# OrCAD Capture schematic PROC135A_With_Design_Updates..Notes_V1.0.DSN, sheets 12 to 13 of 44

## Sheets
12 12. SOC POWER SUPPLY PMIC: size C; title: SOC POWER SUPPLY PMIC
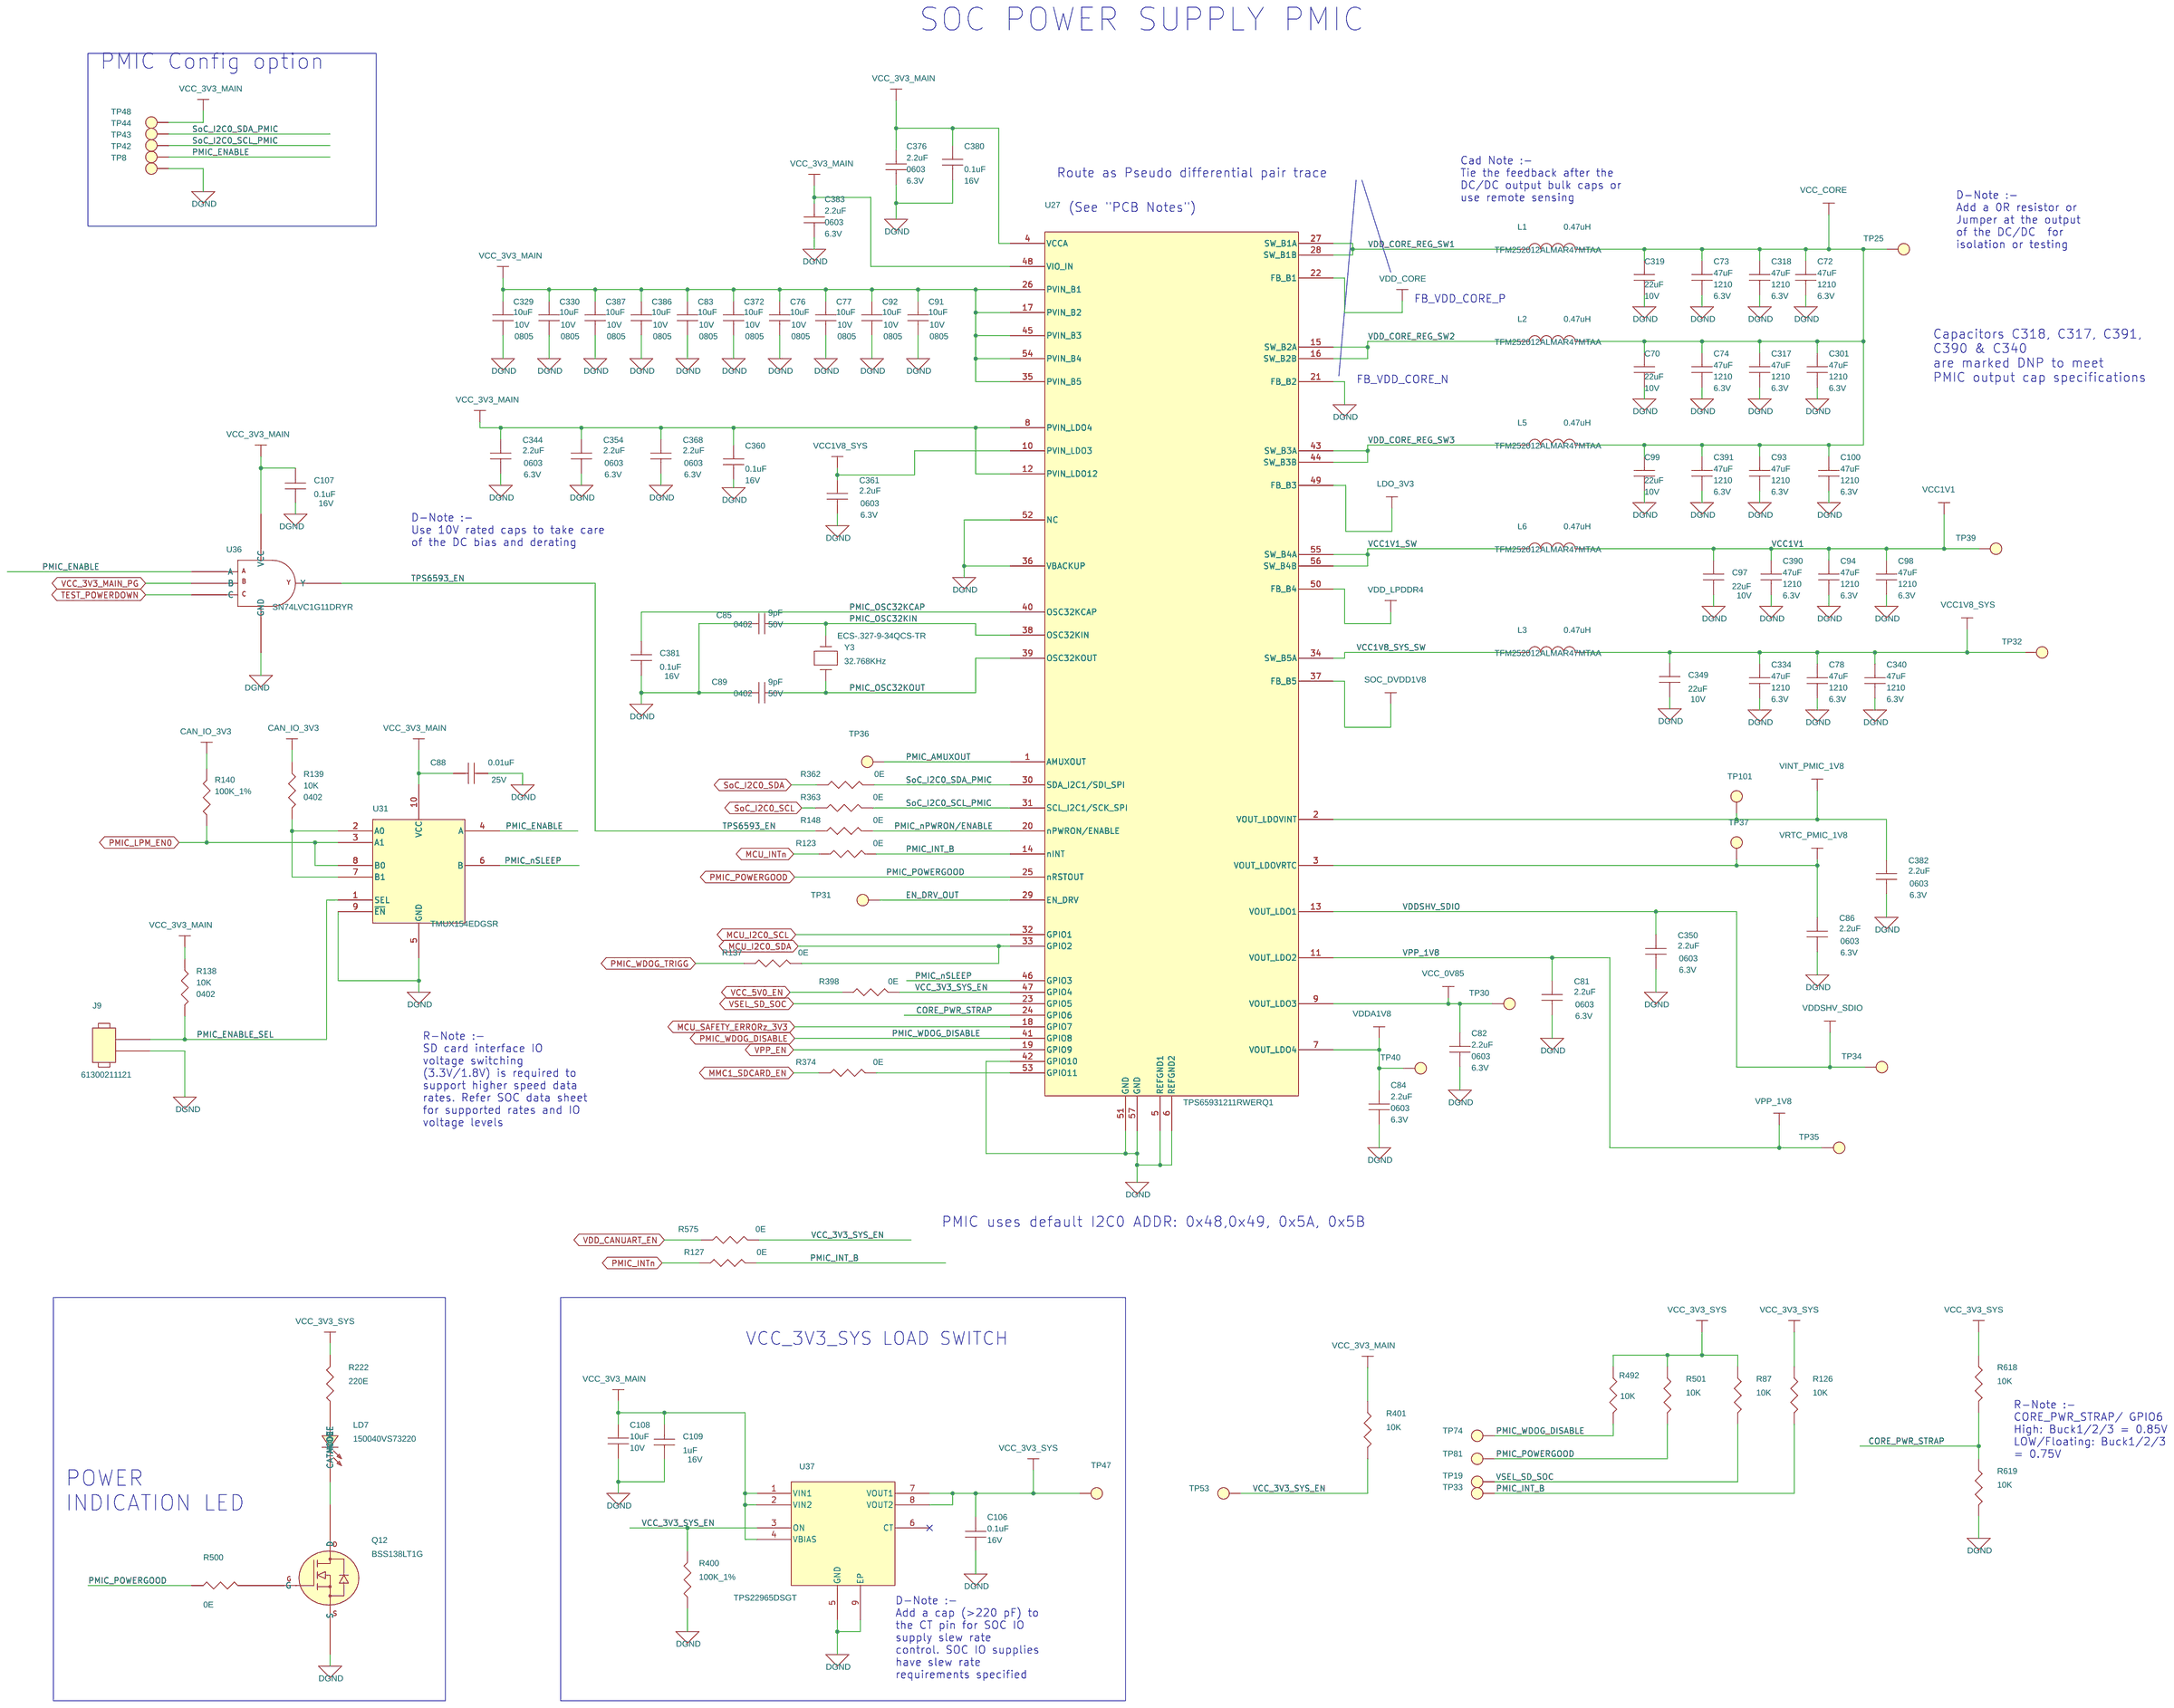
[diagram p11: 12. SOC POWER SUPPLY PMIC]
13 13. CURRENT MONITORING DEVICES: size C; title: CURRENT MONITORING DEVICES
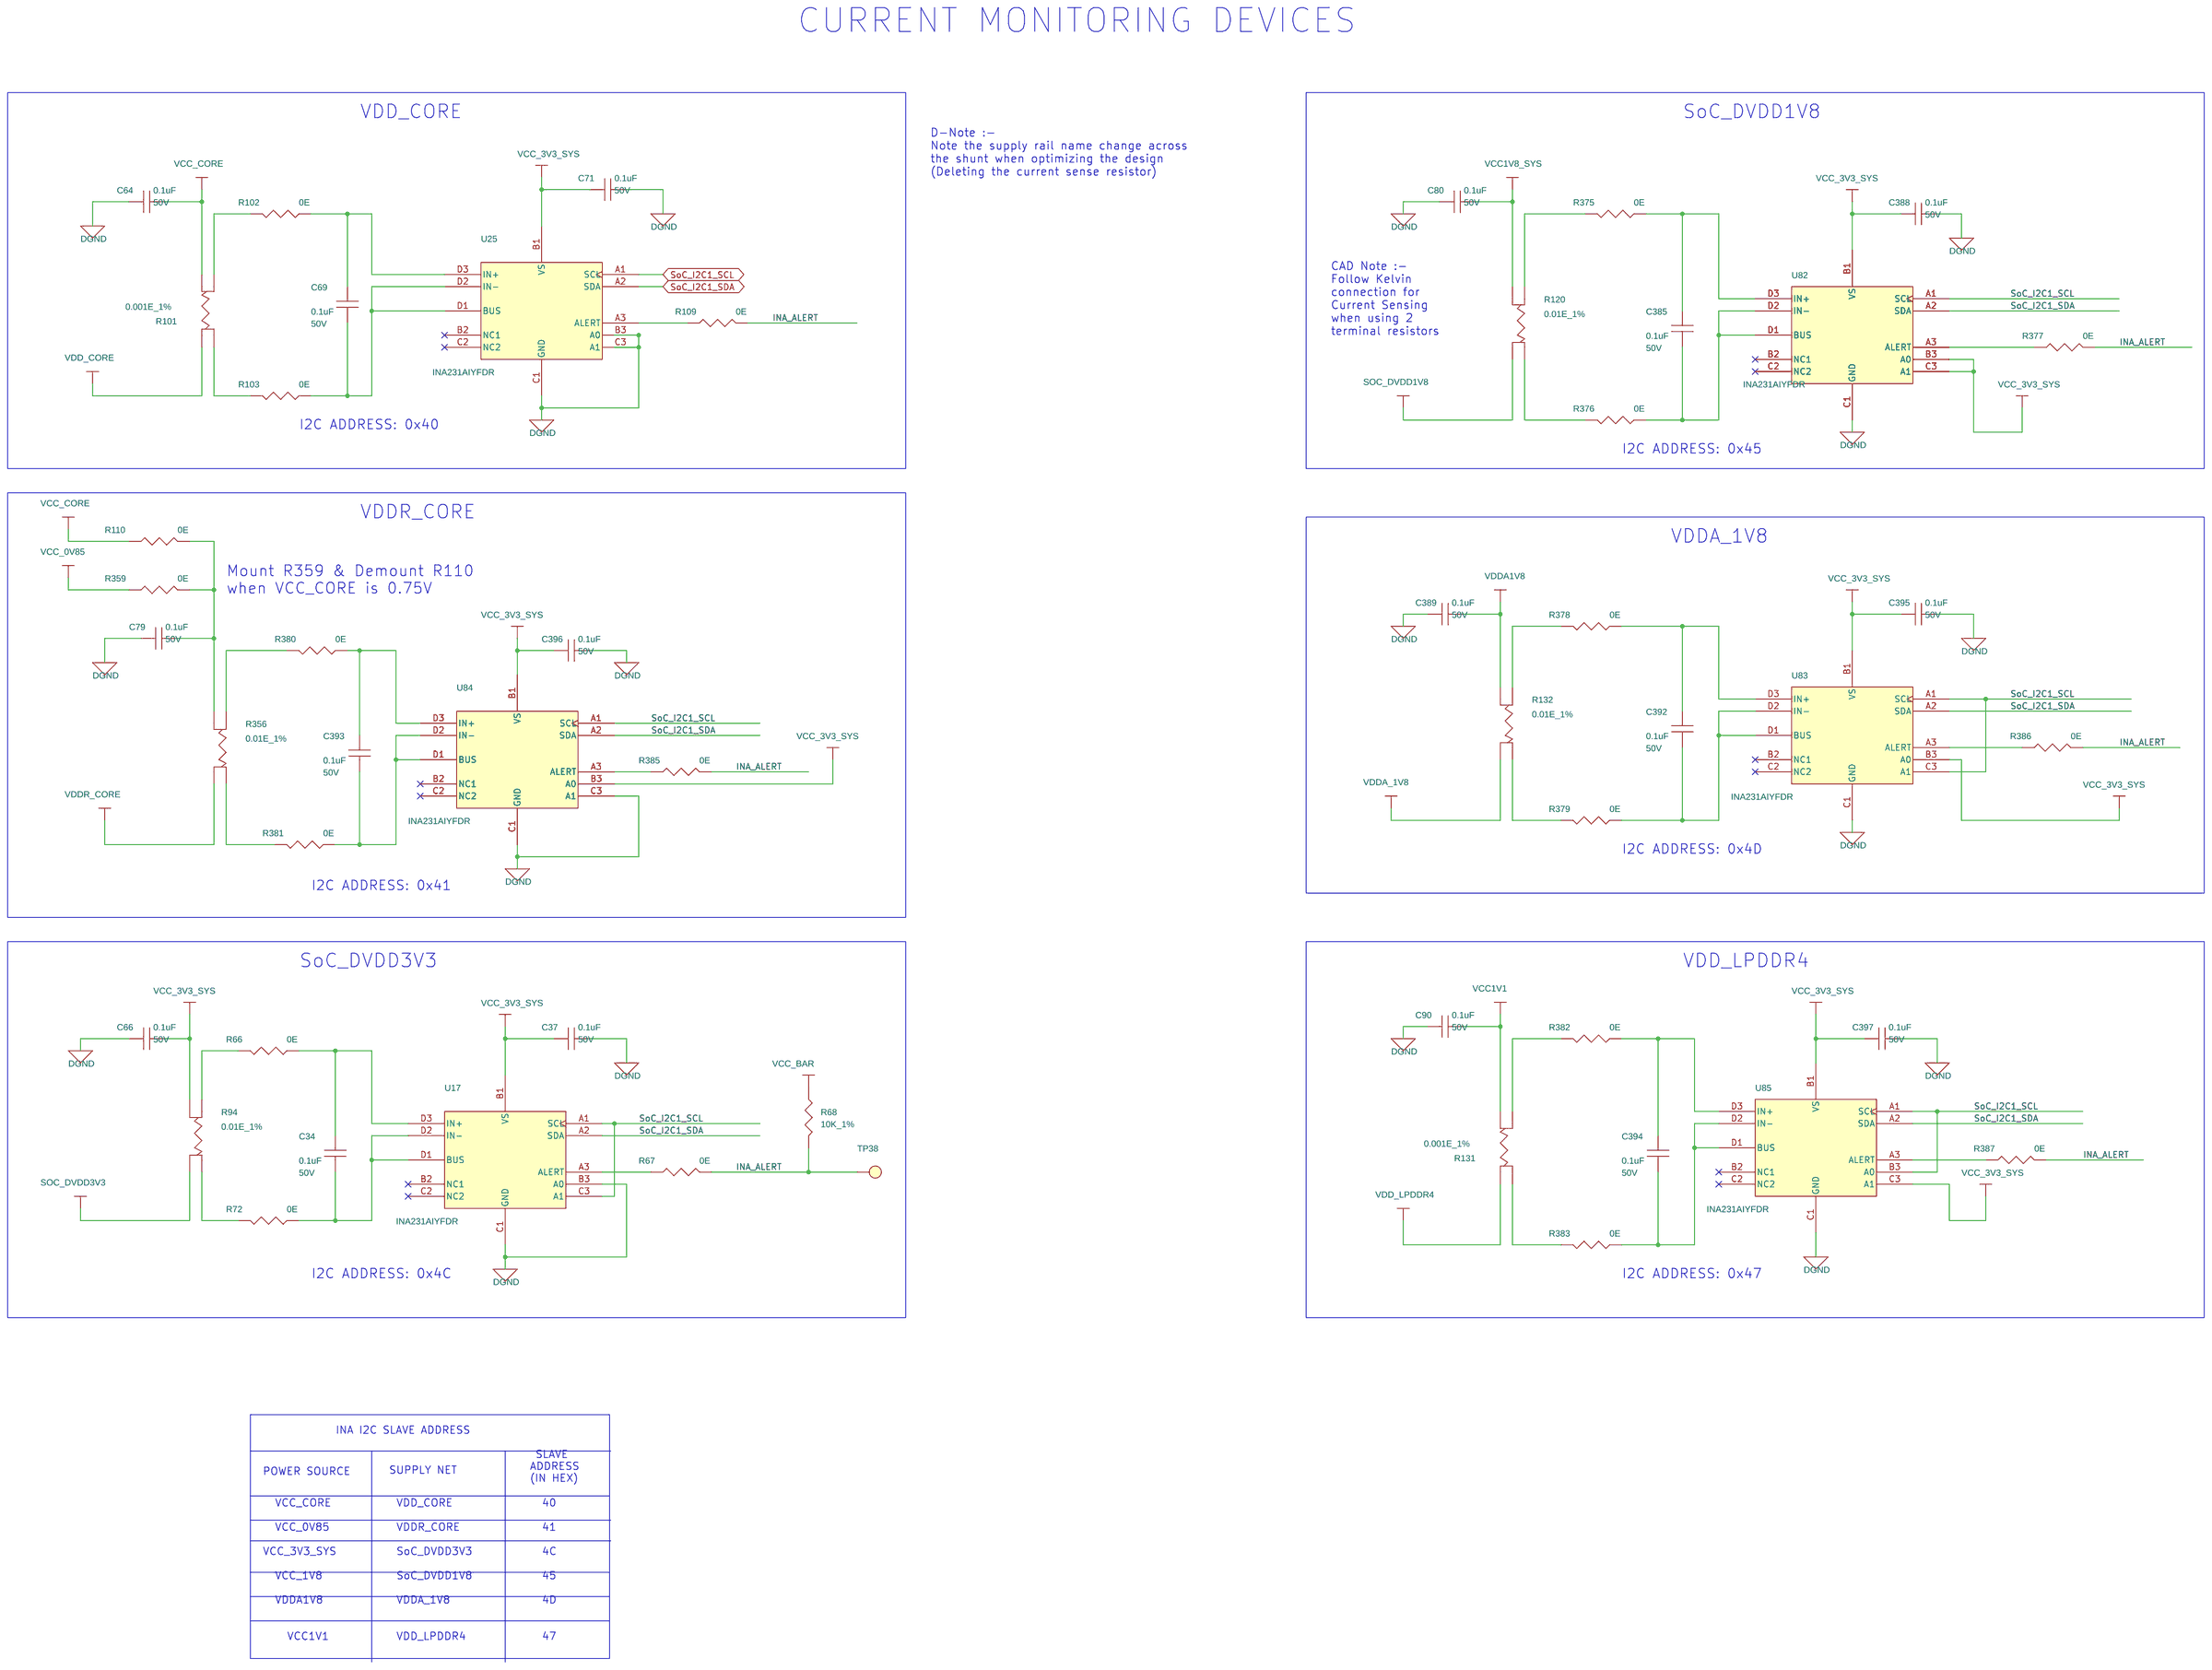
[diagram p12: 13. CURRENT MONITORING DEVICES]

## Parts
sheet 12. SOC POWER SUPPLY PMIC
C70  22uF  [CAP0603_1]
C72  47uF  [CAP1210_2-75]
C73  47uF  [CAP1210_2-75]
C74  47uF  [CAP1210_2-75]
C76  10uF  [CAP0805_1-5]
C77  10uF  [CAP0805_1-5]
C78  47uF  [CAP1210_2-75]
C81  2.2uF  [CAP0603_1]
C82  2.2uF  [CAP0603_1]
C83  10uF  [CAP0805_1-5]
C84  2.2uF  [CAP0603_1]
C85  9pF  [CAP0402_0-75]
C86  2.2uF  [CAP0603_1]
C88  0.01uF  [CAP0201_0-5]
C89  9pF  [CAP0402_0-75]
C91  10uF  [CAP0805_1-5]
C92  10uF  [CAP0805_1-5]
C93  47uF  [CAP1210_2-75]
C94  47uF  [CAP1210_2-75]
C97  22uF  [CAP0603_1]
C98  47uF  [CAP1210_2-75]
C99  22uF  [CAP0603_1]
C100  47uF  [CAP1210_2-75]
C106  0.1uF  [CAP0201_0-5]
C107  0.1uF  [CAP0201_0-5]
C108  10uF  [CAP0402_0-75]
C109  1uF  [CAP0201_0-5]
C301  47uF  [CAP1210_2-75]
C317  47uF  [CAP1210_2-75]
C318  47uF  [CAP1210_2-75]
C319  22uF  [CAP0603_1]
C329  10uF  [CAP0805_1-5]
C330  10uF  [CAP0805_1-5]
C334  47uF  [CAP1210_2-75]
C340  47uF  [CAP1210_2-75]
C344  2.2uF  [CAP0603_1]
C349  22uF  [CAP0603_1]
C350  2.2uF  [CAP0603_1]
C354  2.2uF  [CAP0603_1]
C360  0.1uF  [CAP0201_0-5]
C361  2.2uF  [CAP0603_1]
C368  2.2uF  [CAP0603_1]
C372  10uF  [CAP0805_1-5]
C376  2.2uF  [CAP0603_1]
C380  0.1uF  [CAP0201_0-5]
C381  0.1uF  [CAP0201_0-5]
C382  2.2uF  [CAP0603_1]
C383  2.2uF  [CAP0603_1]
C386  10uF  [CAP0805_1-5]
C387  10uF  [CAP0805_1-5]
C390  47uF  [CAP1210_2-75]
C391  47uF  [CAP1210_2-75]
J9  HDR_1X2  [HDR_1X2_61300211121_S_T_8-6]
L1  0.47uH  [IND1008_1-2]
L2  0.47uH  [IND1008_1-2]
L3  0.47uH  [IND1008_1-2]
L5  0.47uH  [IND1008_1-2]
L6  0.47uH  [IND1008_1-2]
LD7  150040VS73220  [LED_150040GS73220_40X20_SMD_0-4]
Q12  BSS138LT1G  [SOT23-123_1-2]
R87  10K  [RES0201_0-5]
R123  0E  [RES0201_0-5]
R126  10K  [RES0201_0-5]
R127  0E  [RES0201_0-5]
R137  0E  [RES0201_0-5]
R138  10K  [RES0402_0-5]
R139  10K  [RES0402_0-5]
R140  100K_1%  [RES0402_0-5]
R148  0E  [RES0201_0-5]
R222  220E  [RES0402_0-5]
R362  0E  [RES0201_0-5]
R363  0E  [RES0201_0-5]
R374  0E  [RES0201_0-5]
R398  0E  [RES0201_0-5]
R400  100K_1%  [RES0402_0-5]
R401  10K  [RES0201_0-5]
R492  10K  [RES0201_0-5]
R500  0E  [RES0201_0-5]
R501  10K  [RES0201_0-5]
R575  0E  [RES0201_0-5]
R618  10K  [RES0201_0-5]
R619  10K  [RES0201_0-5]
TP8  TP40_SMD  [TP40_SMD]
TP19  TP20_SMD  [TP20_SMD]
TP25  TP20_SMD  [TP20_SMD]
TP30  TP20_SMD  [TP20_SMD]
TP31  TP30_SMD  [TP30_SMD]
TP32  TP20_SMD  [TP20_SMD]
TP33  TP20_SMD  [TP20_SMD]
TP34  TP20_SMD  [TP20_SMD]
TP35  TP20_SMD  [TP20_SMD]
TP36  TP20_SMD  [TP20_SMD]
TP37  TP20_SMD  [TP20_SMD]
TP39  TP20_SMD  [TP20_SMD]
TP40  TP20_SMD  [TP20_SMD]
TP42  TP40_SMD  [TP40_SMD]
TP43  TP40_SMD  [TP40_SMD]
TP44  TP40_SMD  [TP40_SMD]
TP47  TP20_SMD  [TP20_SMD]
TP48  TP40_SMD  [TP40_SMD]
TP53  TP20_SMD  [TP20_SMD]
TP74  TP30_SMD  [TP30_SMD]
TP81  TP20_SMD  [TP20_SMD]
TP101  TP20_SMD  [TP20_SMD]
U27  TPS65931211RWERQ1  [VQFN56_19-68_320X320_0-9_EP6]
U31  TMUX154EDGSR  [MSOP10_19-68_120X120_1-1]
U36  SN74LVC1G11DRYR  [SON6_SN74LVC2G17_40X60_0-6]
U37  TPS22965DSGT  [WSON8_19-68_80X80_0-8]
Y3  32.768KHz  [XTAL_ECS-32_130X60_SMD_0-9]
sheet 13. CURRENT MONITORING DEVICES
C34  0.1uF  [CAP0402_0-75]
C37  0.1uF  [CAP0402_0-75]
C64  0.1uF  [CAP0402_0-75]
C66  0.1uF  [CAP0402_0-75]
C69  0.1uF  [CAP0402_0-75]
C71  0.1uF  [CAP0402_0-75]
C79  0.1uF  [CAP0402_0-75]
C80  0.1uF  [CAP0402_0-75]
C90  0.1uF  [CAP0402_0-75]
C385  0.1uF  [CAP0402_0-75]
C388  0.1uF  [CAP0402_0-75]
C389  0.1uF  [CAP0402_0-75]
C392  0.1uF  [CAP0402_0-75]
C393  0.1uF  [CAP0402_0-75]
C394  0.1uF  [CAP0402_0-75]
C395  0.1uF  [CAP0402_0-75]
C396  0.1uF  [CAP0402_0-75]
C397  0.1uF  [CAP0402_0-75]
R66  0E  [RES0402_0-5]
R67  0E  [RES0201_0-5]
R68  10K_1%  [RES0201_0-5]
R72  0E  [RES0402_0-5]
R94  0.01E_1%  [RES_KRL3216T4_1206-4_0-7]
R101  0.001E_1%  [RES_CST0612_0612-4_0-9]
R102  0E  [RES0402_0-5]
R103  0E  [RES0402_0-5]
R109  0E  [RES0201_0-5]
R110  0E  [RES0603_0-75]
R120  0.01E_1%  [RES_KRL3216T4_1206-4_0-7]
R131  0.001E_1%  [RES_CST0612_0612-4_0-9]
R132  0.01E_1%  [RES_KRL3216T4_1206-4_0-7]
R356  0.01E_1%  [RES_KRL3216T4_1206-4_0-7]
R359  0E  [RES0603_0-75]
R375  0E  [RES0402_0-5]
R376  0E  [RES0402_0-5]
R377  0E  [RES0201_0-5]
R378  0E  [RES0402_0-5]
R379  0E  [RES0402_0-5]
R380  0E  [RES0402_0-5]
R381  0E  [RES0402_0-5]
R382  0E  [RES0402_0-5]
R383  0E  [RES0402_0-5]
R385  0E  [RES0201_0-5]
R386  0E  [RES0201_0-5]
R387  0E  [RES0201_0-5]
TP38  TP20_SMD  [TP20_SMD]
U17  INA231AIYFDR  [DSBGA12_15-74_60X70_0-4]
U25  INA231AIYFDR  [DSBGA12_15-74_60X70_0-4]
U82  INA231AIYFDR  [DSBGA12_15-74_60X70_0-4]
U83  INA231AIYFDR  [DSBGA12_15-74_60X70_0-4]
U84  INA231AIYFDR  [DSBGA12_15-74_60X70_0-4]
U85  INA231AIYFDR  [DSBGA12_15-74_60X70_0-4]

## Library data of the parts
C70 C97 C99 C319 C349 = CAP: CAP CERAMIC 22uF 10V 20% X5R 0603; Chkd/date: MANIRAJA/230118; Crtd /date: MANIRAJA/230118; Custom_Duty: 15%; Customs_HS_Code: 85322990; Distributor_name: DIGIKEY; Distributor_part_number: 490-10476-1-ND; Footprint Path: Y:\MIS_DATABASE\Library\ALTIUM_TOOL\PCB_FOOTPRINTS\Altium_Footprint_Lib.PcbLib; Height: 1.00MM; Library Path: Y:\MIS_DATABASE\Library\ALTIUM_TOOL\SCHEMATICS_PARTS\MS_DISCRETE_Library.schlib; Manufacturer: MURATA; Mfr_name: MURATA; Mfr_part_number: GRM188R61A226ME15D; Mistral Part No: 120014100009-R; Package: 0603; Part_type: CAPACITORS\CERAMIC; Project: TI_MAXIE_CPB; RoHS: RoHS; Temperature: -55°C+85°C; Tolerance: 20%; Voltage: 10V; Wattage: NA; Weight: 6.3mg; Datasheet: Y:\MIS_DATABASE\DATASHEETS\CAPACITORS\GRM188R61A226ME15.PDF
C72-C74 C78 C93 C94 C98 C100 C301 C317 C318 C334 C340 C390 C391 = CAP: CAP CERAMIC 47uF 6.3V 10% X7R AUTO 1210; Automotive Alternate_mfr_name: TDK; Automotive Alternate_mfr_part_number: CGA6P1X7S1A476M; Chkd/date: MANIRAJA/280918; Crtd /date: ALVY/280918; Custom_Duty: 15%; Customs_HS_Code: 85322990; Direct Alternate_mfr_name: TDK; Direct Alternate_mfr_part_number: CGA6P1X7S1A476M; Distributor_name: DIGIKEY; Distributor_part_number: 490-4844-1-ND; Footprint Path: Y:\MIS_DATABASE\Library\ALTIUM_TOOL\PCB_FOOTPRINTS\Altium_Footprint_Lib.PcbLib; Height: 2.70MM; Library Path: Y:\MIS_DATABASE\Library\ALTIUM_TOOL\SCHEMATICS_PARTS\MS_DISCRETE_Library.schlib; Mfr_name: MURATA; Mfr_part_number: GCM32ER70J476KE19L; Mistral Part No: 120018090056-R; Package: 1210; Part_type: CAPACITORS\CERAMIC; Project: TI_J7_SVB-DUT; RoHS: RoHS; Temperature: -55°C+125°C; Tolerance: 10%; Voltage: 6.3V; Wattage: NA; Weight: 110mg; Datasheet: Y:\MIS_DATABASE\DATASHEETS\CAPACITORS\MURATA-GCM-SER.PDF
C76 C77 C83 C91 C92 C329 C330 C372 C386 C387 = CAP: CAP CERAMIC 10uF 10V 10% X7R AUTO 0805; Automotive Alternate_mfr_name: MURATA; Automotive Alternate_mfr_part_number: GCM21BR71A106KE22L; Chkd/date: MANIRAJA/080419; Crtd /date: ALVY/050419; Custom_Duty: 15%; Customs_HS_Code: 85322990; Direct Alternate_mfr_name: SAMSUNG; Direct Alternate_mfr_part_number: CL21B106KPQNNNE; Distributor_name: DIGIKEY; Distributor_part_number: 490-14531-1-ND; Footprint Path: Y:\MIS_DATABASE\Library\ALTIUM_TOOL\PCB_FOOTPRINTS\Altium_Footprint_Lib.PcbLib; Height: 1.40MM; Library Path: Y:\MIS_DATABASE\Library\ALTIUM_TOOL\SCHEMATICS_PARTS\MS_DISCRETE_Library.schlib; Mfr_name: MURATA; Mfr_part_number: GCM21BR71A106KE22K; Mistral Part No: 120019040010-R; Package: 0805; Part_type: CAPACITORS\CERAMIC; Project: J7ES_SOM_DUAL-LEO_PMIC; RoHS: RoHS; Temperature: -55°C+125°C; Tolerance: 10%; Voltage: 10V; Wattage: NA; Weight: 9.5mg; Datasheet: Y:\MIS_DATABASE\DATASHEETS\CAPACITORS\GCM21BR71A106KE22.PDF
C81 C82 C84 C86 C344 C350 C354 C361 C368 C376 C382 C383 = CAP: CAP CERAMIC 2.2uF 6.3V 10% X7R AUTO 0603; Automotive Alternate_mfr_name: TDK; Automotive Alternate_mfr_part_number: CGA3E1X7R0J225K080AC; Chkd/date: MANIRAJA/050419; Crtd /date: ALVY/050419; Custom_Duty: 15%; Customs_HS_Code: 85322990; Direct Alternate_mfr_name: TDK; Direct Alternate_mfr_part_number: CGA3E1X7R0J225K080AC; Distributor_name: DIGIKEY; Distributor_part_number: 490-5316-1-ND; Footprint Path: Y:\MIS_DATABASE\Library\ALTIUM_TOOL\PCB_FOOTPRINTS\Altium_Footprint_Lib.PcbLib; Height: 0.90MM; Library Path: Y:\MIS_DATABASE\Library\ALTIUM_TOOL\SCHEMATICS_PARTS\MS_DISCRETE_Library.schlib; Mfr_name: MURATA; Mfr_part_number: GCM188R70J225KE22D; Mistral Part No: 120019040009-R; Package: 0603; Part_type: CAPACITORS\CERAMIC; Project: J7ES_SOM_DUAL-LEO_PMIC; RoHS: RoHS; Temperature: -55°C+125°C; Tolerance: 10%; Voltage: 6.3V; Wattage: NA; Weight: 6.3mg; Datasheet: Y:\MIS_DATABASE\DATASHEETS\CAPACITORS\GCM188R70J225KE22.PDF
C85 C89 = CAP: CAP CERAMIC 9pF 50V 0.5pF C0G(NP0) AUTO 0402; Automotive Alternate_mfr_name: TDK; Automotive Alternate_mfr_part_number: CGA2B2C0G1H090D050BA; Chkd/date: MANIRAJA/290121; Crtd /date: ALVY/270121; Custom_Duty: 15%; Customs_HS_Code: 85322990; Direct Alternate_mfr_name: TDK; Direct Alternate_mfr_part_number: CGA2B2C0G1H090D050BA; Distributor_name: DIGIKEY; Distributor_part_number: GCM1555C1H9R0DA16D-ND; Footprint Path: Y:\MIS_DATABASE\Library\ALTIUM_TOOL\PCB_FOOTPRINTS\Altium_Footprint_Lib.PcbLib; Height: 0.55MM; Library Path: Y:\MIS_DATABASE\Library\ALTIUM_TOOL\SCHEMATICS_PARTS\MS_DISCRETE_Library.schlib; Mfr_name: MURATA; Mfr_part_number: GCM1555C1H9R0DA16D; Mistral Part No: 120021010034-R; Package: 0402; Part_type: CAPACITORS\CERAMIC; Project: TI_DRA829 SK EVM BRD; RoHS: RoHS; Temperature: -55°C+125°C; Tolerance: 0.5pF%; Voltage: 50V; Wattage: NA; Weight: 1.6mg; Datasheet: Y:\MIS_DATABASE\DATASHEETS\CAPACITORS\MURATA-GCM-SER.PDF
C88 = CAP: CAP CERAMIC 0.01uF 25V 10% X5R 0201; Chkd/date: MANIRAJA/230118; Crtd /date: MANIRAJA/230118; Custom_Duty: 15%; Customs_HS_Code: 85322990; Distributor_name: DIGIKEY; Distributor_part_number: GRM033R61E103KA12J-ND; Footprint Path: Y:\MIS_DATABASE\Library\ALTIUM_TOOL\PCB_FOOTPRINTS\Altium_Footprint_Lib.PcbLib; Height: 0.33MM; Library Path: Y:\MIS_DATABASE\Library\ALTIUM_TOOL\SCHEMATICS_PARTS\MS_DISCRETE_Library.schlib; Mfr_name: MURATA; Mfr_part_number: GRM033R61E103KA12J; Mistral Part No: 120018010007-R; Package: 0201; Part_type: CAPACITORS\CERAMIC; Project: TI_MAXIE_CPB; RoHS: RoHS; Temperature: -55°C+85°C; Tolerance: 10%; Voltage: 25V; Wattage: NA; Weight: 0.33mg; Datasheet: Y:\MIS_DATABASE\DATASHEETS\CAPACITORS\GRM033R61E103KA12.PDF
C106 C107 = CAP: CAP CERAMIC 0.1uF 16V 10% X5R 0201; Alt_Mfr_name: YAGEO AMERICA; Alt_Mfr_part_number: CC0402KRX5R8BB104; Chkd/date: MANIRAJA/230118; Crtd /date: MANIRAJA/230118; Custom_Duty: 15%; Customs_HS_Code: 85322990; Distributor_name: DIGIKEY; Distributor_part_number: 490-14305-1-ND; Footprint Path: Y:\MIS_DATABASE\Library\ALTIUM_TOOL\PCB_FOOTPRINTS\Altium_Footprint_Lib.PcbLib; Height: 0.33MM; Library Path: Y:\MIS_DATABASE\Library\ALTIUM_TOOL\SCHEMATICS_PARTS\MS_DISCRETE_Library.schlib; Mfr_name: MURATA; Mfr_part_number: GRM033R61C104KE14D; Mistral Part No: 120009030072-R; Package: 0201; Part_type: CAPACITORS\CERAMIC; Project: TI_MAXIE_CPB; RoHS: RoHS; Temperature: -55°C+85°C; Tolerance: 10%; Voltage: 16V; Wattage: NA; Weight: 0.33mg; Datasheet: Y:\MIS_DATABASE\DATASHEETS\CAPACITORS\GRM033R61C104KE14.PDF
C108 = CAP: CAP CERAMIC 10uF 10V 20% X5R 0402; Chkd/date: MANIRAJA/300520; Crtd /date: ALVY/260520; Custom_Duty: 15%; Customs_HS_Code: 85322990; Distributor_name: DIGIKEY; Distributor_part_number: 490-GRM155R61A106ME11DTR-ND; Footprint Path: Y:\MIS_DATABASE\Library\ALTIUM_TOOL\PCB_FOOTPRINTS\Altium_Footprint_Lib.PcbLib; Height: 0.55MM; Library Path: Y:\MIS_DATABASE\Library\ALTIUM_TOOL\SCHEMATICS_PARTS\MS_DISCRETE_Library.schlib; Mfr_name: MURATA; Mfr_part_number: GRM155R61A106ME11D; Mistral Part No: 120013110019-R; Package: 0402; Part_type: CAPACITORS\CERAMIC; Project: QCS610_NANOSOM; RoHS: RoHS; Temperature: -55°C+85°C; Tolerance: 20%; Voltage: 10V; Wattage: NA; Weight: 3.1mg; Datasheet: Y:\MIS_DATABASE\DATASHEETS\CAPACITORS\MURATA-GXX-SER_NOV17.PDF
C109 = CAP: CAP CERAMIC 1uF 16V 20% X5R 0201; Chkd/date: MANIRAJA/300520; Crtd /date: ALVY/260520; Custom_Duty: 15%; Customs_HS_Code: 85322990; Distributor_name: DIGIKEY; Distributor_part_number: 490-18654-1-ND; Footprint Path: Y:\MIS_DATABASE\Library\ALTIUM_TOOL\PCB_FOOTPRINTS\Altium_Footprint_Lib.PcbLib; Height: 0.39MM; Library Path: Y:\MIS_DATABASE\Library\ALTIUM_TOOL\SCHEMATICS_PARTS\MS_DISCRETE_Library.schlib; Mfr_name: MURATA; Mfr_part_number: GRM033R61C105ME15D; Mistral Part No: 120018090038-R; Package: 0201; Part_type: CAPACITORS\CERAMIC; Project: QCS610_NANOSOM; RoHS: RoHS; Temperature: -55°C+85°C; Tolerance: 20%; Voltage: 16V; Wattage: NA; Weight: 0.33mg; Datasheet: Y:\MIS_DATABASE\DATASHEETS\CAPACITORS\GRM033R61C105ME15.PDF
C360 C380 C381 = CAP: CAP CERAMIC 0.1uF 16V 10% X7S AUTO 0201; Chkd/date: MANIRAJA/110321; Crtd /date: ALVY/110321; Custom_Duty: 15%; Customs_HS_Code: 85322990; Distributor_name: DIGIKEY; Distributor_part_number: 490-GRT033C71C104KE01DTR-ND; Height: 0.33MM; Mfr_name: MURATA; Mfr_part_number: GRT033C71C104KE01D; Mistral Part No: 120021030007-R; Package: 0201; Part_type: CAPACITORS\CERAMIC; Project: J7ES_SK_BRD; RoHS: RoHS; Temperature: -55°C+125°C; Tolerance: 10%; Voltage: 16V; Wattage: NA; Weight: 330mg; Datasheet: Y:\MIS_DATABASE\DATASHEETS\CAPACITORS\GRT033C71C104KE01.PDF
J9 = HEADER_2X1: CON HDR 1X2 2.54MM PITCH ST TH; Chkd/date: MANIRAJA/031018; Crtd /date: ALVY/031018; Custom_Duty: 24%; Customs_HS_Code: 85369090; Distributor_name: DIGIKEY; Distributor_part_number: 732-5315-ND; Footprint Path: Y:\MIS_DATABASE\Library\ALTIUM_TOOL\PCB_FOOTPRINTS\Altium_Footprint_Lib.PcbLib; Height: 8.54MM; Library Path: Y:\MIS_DATABASE\Library\ALTIUM_TOOL\SCHEMATICS_PARTS\MS_CONNECTOR_Library.schlib; Mfr_name: WURTH ELECTRONICS; Mfr_part_number: 61300211121; Mistral Part No: 150018100003-R; Package: THRU-HOLE; Part_type: CONNECTOR\HEADERS; Project: ALPINE_EVM; RoHS: RoHS; Temperature: -40°C+105°C; Tolerance: NA; Voltage: NA; Wattage: NA; Weight: 120mg; Datasheet: Y:\MIS_DATABASE\DATASHEETS\CONNECTORS\6130XXX.PDF
L1-L3 L5 L6 = INDUCTOR: IND POWER 0.47uH 20% 4.9A 1008; Chkd/date: VASANTHA/010419; Crtd /date: ALVY/010419; Custom_Duty: 24%; Customs_HS_Code: 85437099; Distributor_name: DIGIKEY; Distributor_part_number: 445-181489-1-ND; Footprint Path: Y:\MIS_DATABASE\Library\ALTIUM_TOOL\PCB_FOOTPRINTS\Altium_Footprint_Lib.PcbLib; Height: 1.20MM; Library Path: Y:\MIS_DATABASE\Library\ALTIUM_TOOL\SCHEMATICS_PARTS\MS_DISCRETE_Library.schlib; Mfr_name: TDK CORPORATION; Mfr_part_number: TFM252012ALMAR47MTAA; Mistral Part No: 130019040001-R; Package: 1008; Project: J7ES_SOM_DUAL-LEO_PMIC; RoHS: RoHS; Temperature: -55°C+150°C; Tolerance: 20%; Voltage: NA; Wattage: NA; Weight: NA; Datasheet: Y:\MIS_DATABASE\DATASHEETS\DISCRETES\INDUCTORS\TFM252012ALMA-SER.PDF
LD7 = DIODE_LED: DIODE LED BRIGHT GREEN SMD; Chkd/date: MANIRAJA/261120; Crtd /date: ALVY/261120; Custom_Duty: 24%; Customs_HS_Code: 85439000; Distributor_name: DIGIKEY; Distributor_part_number: 732-13425-1-ND; Footprint Path: Y:\MIS_DATABASE\Library\ALTIUM_TOOL\PCB_FOOTPRINTS\Altium_Footprint_Lib.PcbLib; Height: 0.35MM; Library Path: Y:\MIS_DATABASE\Library\ALTIUM_TOOL\SCHEMATICS_PARTS\MS_OPTO_Library.schlib; Mfr_name: WURTH ELECTRONIK; Mistral Part No: 130020110071-R; Package: SMD; Part_type: OPTO\LED; Project: AM64X_SKEVM; RoHS: RoHS; Temperature: -40°C+85°C; Tolerance: NA; Voltage: NA; Wattage: NA; Weight: 29.3mg; Datasheet: Y:\MIS_DATABASE\DATASHEETS\DISCRETES\LEDS\150040VS73220.PDF
Q12 = MOSFET_BSS138W: IC MOSFET N-CHANNEL 50V 200mA SOT23-3; Chkd/date: MANIRAJA/250219; Crtd /date: JEBRAN/060416; Custom_Duty: 15%; Customs_HS_Code: 85423100; Distributor_name: DIGIKEY; Distributor_part_number: BSS138LT1GOSCT-ND; Footprint Path: Y:\MIS_DATABASE\Library\ALTIUM_TOOL\PCB_FOOTPRINTS\Altium_Footprint_Lib.PcbLib; Height: 1.11MM; Library Path: Y:\MIS_DATABASE\Library\ALTIUM_TOOL\SCHEMATICS_PARTS\MS_MOSFET_Library.schlib; Mfr_name: ON SEMICONDUCTOR; Mistral Part No: 142016040001-R; Package: SOT23-3; Part_type: ICS\POWER\MOSFET; Project: LRDE_ABCM; RoHS: RoHS; Temperature: -55°C+150°C; Tolerance: NA; Voltage: NA; Wattage: NA; Weight: 8mg; Datasheet: Y:\MIS_DATABASE\DATASHEETS\DISCRETES\TRANSISTORS_FETS\BSS138LT1G.PDF
R87 R126 R401 R492 R501 R618 R619 = RESISTOR: RES 10K 1/20W 5% 0201; Chkd/date: MANIRAJA/050517; Crtd /date: MANIRAJA/050517; Custom_Duty: 15%; Customs_HS_Code: 85332119; Distributor_name: DIGIKEY; Distributor_part_number: 311-10KNCT-ND; Footprint Path: Y:\MIS_DATABASE\Library\ALTIUM_TOOL\PCB_FOOTPRINTS\Altium_Footprint_Lib.PcbLib; Height: 0.26MM; Library Path: Y:\MIS_DATABASE\Library\ALTIUM_TOOL\SCHEMATICS_PARTS\MS_DISCRETE_Library.schlib; Mfr_name: YAGEO AMERICA; Mfr_part_number: RC0201JR-0710KL; Mistral Part No: 110010070051-R; Package: 0201; Part_type: RESISTORS\FIXED; Project: GOLDEN-I LITE; RoHS: RoHS; Temperature: -55°C+125°C; Tolerance: 5%; Voltage: NA; Wattage: 1/20W; Weight: 0.17mg; Datasheet: Y:\MIS_DATABASE\DATASHEETS\RESISTORS\RCXXXXL-SER_MAR18.PDF
R67 R109 R123 R137 R374 R377 R385-R387 R398 R575 = RESISTOR: RES 0E 1/20W 5% 0201; Chkd/date: NAVEED/301214; Crtd /date: MUDDU/120710; Custom_Duty: 15%; Customs_HS_Code: 85332119; Distributor_name: DIGIKEY; Distributor_part_number: 311-0.0NCT-ND; Footprint Path: Y:\MIS_DATABASE\Library\ALTIUM_TOOL\PCB_FOOTPRINTS\Altium_Footprint_Lib.PcbLib; Height: 0.26MM; Library Path: Y:\MIS_DATABASE\Library\ALTIUM_TOOL\SCHEMATICS_PARTS\MS_DISCRETE_Library.schlib; Mfr_name: YAGEO AMERICA; Mfr_part_number: RC0201JR-070RL; Mistral Part No: 110010070067-R; Package: 0201; Part_type: RESISTORS\FIXED; Project: PB_BUGBASE; RoHS: RoHS; Temperature: -55°C+125°C; Tolerance: 5%; Voltage: NA; Wattage: 1/20W; Weight: 0.17mg; Datasheet: Y:\MIS_DATABASE\DATASHEETS\RESISTORS\RCXXXXL-SER_MAR18.PDF
R127 R148 R362 R363 R500 = RESISTOR: RES 0E 1/20W JUMPER 0201; Chkd/date: MANIRAJA/290421; Crtd /date: ALVY/290421; Custom_Duty: 15%; Customs_HS_Code: 85332119; Distributor_name: DIGIKEY; Distributor_part_number: P15979CT-ND; Footprint Path: Y:\MIS_DATABASE\Library\ALTIUM_TOOL\PCB_FOOTPRINTS\Altium_Footprint_Lib.PcbLib; Height: 0.26MM; Library Path: Y:\MIS_DATABASE\Library\ALTIUM_TOOL\SCHEMATICS_PARTS\MS_DISCRETE_Library.schlib; Mfr_name: PANASONIC-ECG; Mfr_part_number: ERJ-1GN0R00C; Mistral Part No: 110009030078-R; Package: 0201; Part_type: RESISTORS\FIXED; Project: SRMS-SAR_BRD; RoHS: RoHS; Temperature: -55°C+125°C; Tolerance: NA; Voltage: NA; Wattage: 1/20W; Weight: 0.15mg; Datasheet: Y:\MIS_DATABASE\DATASHEETS\RESISTORS\PAN-ERJSER_NOV17.PDF
R138 R139 = RESISTOR: RES 10K 1/16W 5% 0402; Chkd/date: VASANTHA/061216; Crtd /date: MAZHAR/230805; Custom_Duty: 15%; Customs_HS_Code: 85332119; Distributor_name: DIGIKEY; Distributor_part_number: 311-10KJRCT-ND; Footprint Path: Y:\MIS_DATABASE\Library\ALTIUM_TOOL\PCB_FOOTPRINTS\Altium_Footprint_Lib.PcbLib; Height: 0.40MM; Library Path: Y:\MIS_DATABASE\Library\ALTIUM_TOOL\SCHEMATICS_PARTS\MS_DISCRETE_Library.schlib; Mfr_name: YAGEO AMERICA; Mfr_part_number: RC0402JR-0710KL; Mistral Part No: 110011060021-R; Package: 0402; Part_type: RESISTORS\FIXED; Project: HSE; RoHS: RoHS; Temperature: -55°C+155°C; Tolerance: 5%; Voltage: NA; Wattage: 1/16W; Weight: 0.65mg; Datasheet: Y:\MIS_DATABASE\DATASHEETS\RESISTORS\RCXXXXL-SER_MAR18.PDF
R140 R400 = RESISTOR: RES 100K 1/10W 1% 0402; Chkd/date: VASANTHA/201216; Crtd /date: MAZHAR/130306; Custom_Duty: 15%; Customs_HS_Code: 85332119; Distributor_name: DIGIKEY; Distributor_part_number: P100KLCT-ND; Footprint Path: Y:\MIS_DATABASE\Library\ALTIUM_TOOL\PCB_FOOTPRINTS\Altium_Footprint_Lib.PcbLib; Height: 0.40MM; Library Path: Y:\MIS_DATABASE\Library\ALTIUM_TOOL\SCHEMATICS_PARTS\MS_DISCRETE_Library.schlib; Mfr_name: PANASONIC-ECG; Mfr_part_number: ERJ-2RKF1003X; Mistral Part No: 110009030187-R; Package: 0402; Part_type: RESISTORS\FIXED; Project: J32; RoHS: RoHS; Temperature: -55°C+155°C; Tolerance: 1%; Voltage: NA; Wattage: 1/10W; Weight: 0.8mg; Datasheet: Y:\MIS_DATABASE\DATASHEETS\RESISTORS\PAN-ERJSER_NOV17.PDF
R222 = RESISTOR: RES 220E 1/10W 5% 0402; Chkd/date: VASANTHA/291216; Crtd /date: GEETHA/260406; Custom_Duty: 15%; Customs_HS_Code: 85332119; Distributor_name: DIGIKEY; Distributor_part_number: P220JCT-ND; Footprint Path: Y:\MIS_DATABASE\Library\ALTIUM_TOOL\PCB_FOOTPRINTS\Altium_Footprint_Lib.PcbLib; Height: 0.40MM; Library Path: Y:\MIS_DATABASE\Library\ALTIUM_TOOL\SCHEMATICS_PARTS\MS_DISCRETE_Library.schlib; Mfr_name: PANASONIC-ECG; Mfr_part_number: ERJ-2GEJ221X; Mistral Part No: 110009030506-R; Package: 0402; Part_type: RESISTORS\FIXED; Project: RED EYE; RoHS: RoHS; Temperature: -55°C+155°C; Tolerance: 5%; Voltage: NA; Wattage: 1/10W; Weight: 0.8mg; Datasheet: Y:\MIS_DATABASE\DATASHEETS\RESISTORS\PAN-ERJSER_NOV17.PDF
TP8 TP42-TP44 TP48 = TESTPOINT: TESTPOINT CIR 40 SMD; Chkd/date: MAZHAR/190505; Crtd /date: MAZHAR/190505; Distributor_name: NA; Distributor_part_number: NA; Footprint Path: Y:\MIS_DATABASE\Library\ALTIUM_TOOL\PCB_FOOTPRINTS\Altium_Footprint_Lib.PcbLib; Height: NA; Library Path: Y:\MIS_DATABASE\Library\ALTIUM_TOOL\SCHEMATICS_PARTS\MS_DISCRETE_Library.schlib; MECHANICAL 3D STEP FILE: NA; Mfr_name: LOCAL; Mistral Part No: 130009030933; Package: SMD; Project: RAINIER-3; RoHS: NA; Temperature: NA; Tolerance: NA; Voltage: NA; Wattage: NA; Weight: NA; Datasheet: NA
TP19 TP33 TP36-TP38 TP47 TP53 TP81 TP101 = TESTPOINT: TESTPOINT CIR 20 SMD; Chkd/date: SHREESHAIL/171006; Crtd /date: MAZHAR/171006; Custom_Duty: NA; Customs_HS_Code: NA; Distributor_name: NA; Distributor_part_number: NA; Footprint Path: Y:\MIS_DATABASE\Library\ALTIUM_TOOL\PCB_FOOTPRINTS\Altium_Footprint_Lib.PcbLib; Height: NA; Library Path: Y:\MIS_DATABASE\Library\ALTIUM_TOOL\SCHEMATICS_PARTS\MS_DISCRETE_Library.schlib; MECHANICAL 3D STEP FILE: NA; Mfr_name: LOCAL; Mistral Part No: NA; Package: SMD; Project: BT MODULE_CSRBC04; RoHS: NA; Temperature: NA; Tolerance: NA; Voltage: NA; Wattage: NA; Weight: NA; Datasheet: NA
TP25 TP30 TP32 TP34 TP35 TP39 TP40 = TESTPOINT: TESTPOINT CIR 20 SMD; Chkd/date: SHREESHAIL/171006; Crtd /date: MAZHAR/171006; Custom_Duty: NA; Customs_HS_Code: NA; Distributor_name: NA; Distributor_part_number: NA; Footprint Path: Y:\MIS_DATABASE\Library\ALTIUM_TOOL\PCB_FOOTPRINTS\Altium_Footprint_Lib.PcbLib; Height: NA; Library Path: Y:\MIS_DATABASE\Library\ALTIUM_TOOL\SCHEMATICS_PARTS\MS_DISCRETE_Library.schlib; MECHANICAL 3D STEP FILE: NA; Manufacturer: LOCAL; Mfr_name: LOCAL; Mistral Part No: NA; Package: SMD; Project: BT MODULE_CSRBC04; RoHS: NA; Temperature: NA; Tolerance: NA; Voltage: NA; Wattage: NA; Weight: NA; Datasheet: NA
TP31 TP74 = TESTPOINT: TESTPOINT CIR 30 SMD; Chkd/date: SHREESHAIL/171006; Crtd /date: MAZHAR/171006; Custom_Duty: NA; Customs_HS_Code: NA; Distributor_name: NA; Distributor_part_number: NA; Footprint Path: Y:\MIS_DATABASE\Library\ALTIUM_TOOL\PCB_FOOTPRINTS\Altium_Footprint_Lib.PcbLib; Height: NA; Library Path: Y:\MIS_DATABASE\Library\ALTIUM_TOOL\SCHEMATICS_PARTS\MS_DISCRETE_Library.schlib; MECHANICAL 3D STEP FILE: NA; Mfr_name: LOCAL; Mistral Part No: 130009030930; Package: SMD; Project: BT MODULE_CSRBC04; RoHS: NA; Temperature: NA; Tolerance: NA; Voltage: NA; Wattage: NA; Weight: NA; Datasheet: NA
U27 = TPS6593-Q1_VQFNP56: IC POWER MANAGEMENT WITH 5 BUCKS AND 4 LDOS FOR SAFETY-RELEVANT AUTOMOTIVE APPLICATIONS VQFNP56; Chkd/date: ALVY/250522; Crtd /date: ALVY/250522; Custom_Duty: 15%; Customs_HS_Code: 85423100; Distributor_name: NA; Distributor_part_number: NA; Footprint Path: Y:\MIS_DATABASE\Library\ALTIUM_TOOL\PCB_FOOTPRINTS\Altium_Footprint_Lib.PcbLib; Height: 0.90MM; Library Path: Y:\MIS_DATABASE\Library\ALTIUM_TOOL\SCHEMATICS_PARTS\MS_MISCPOWER_Library.schlib; Mfr_name: TEXAS INSTRUMENTS; Mistral Part No: 142023080011; Package: VQFN56; Part_type: ICS\POWER\MANAGEMENT; Project: TI_AM62A_SK_EVM; Remarks: FP CREATED AS PER PTPS65941213RWERQ1; RoHS: NA; Temperature: -40°C+125°C; Tolerance: NA; Voltage: NA; Wattage: NA; Weight: NA; Datasheet: Y:\MIS_DATABASE\DATASHEETS\ICS\POWER\TPS6593-Q1.PDF
U31 = TMUX154EDGSR_VSSOP10: IC ESD PROTECTED 2-CH 2:1 SWITCH WITH POWERED-OFF PROTECTION VSSOP10; Chkd/date: MANIRAJA/040918; Crtd /date: MANIRAJA/040918; Custom_Duty: 15%; Customs_HS_Code: 85423100; Distributor_name: DIGIKEY; Distributor_part_number: 296-48347-1-ND; Footprint Path: Y:\MIS_DATABASE\Library\ALTIUM_TOOL\PCB_FOOTPRINTS\Altium_Footprint_Lib.PcbLib; Height: 1.10MM; Library Path: Y:\MIS_DATABASE\Library\ALTIUM_TOOL\SCHEMATICS_PARTS\MS_ANALOG-APPLICATION_Library.schlib; Mfr_name: TEXAS INSTRUMENTS; Mistral Part No: 140118090001-R; Package: VSSOP10; Part_type: ICS\ANALOG\SWITCH; Project: DLRL_DFP_ATRUC CARD; RoHS: RoHS; Temperature: -40°C+85°C; Tolerance: NA; Voltage: NA; Wattage: NA; Weight: NA; Datasheet: Y:\MIS_DATABASE\DATASHEETS\ICS\ANALOG\TMUX154EXXX.PDF
U36 = SN74LVC1G11DCKR_SC70-6: IC SINGLE 3-INPUT POSITIVE-AND GATE SON6; Chkd/date: MANIRAJA/270121; Crtd /date: ALVY/270121; Custom_Duty: 15%; Customs_HS_Code: 85423100; Distributor_name: DIGIKEY; Distributor_part_number: 296-30120-1-ND; Footprint Path: Y:\MIS_DATABASE\Library\ALTIUM_TOOL\PCB_FOOTPRINTS\Altium_Footprint_Lib.PcbLib; Height: 0.60MM; Library Path: Y:\MIS_DATABASE\Library\ALTIUM_TOOL\SCHEMATICS_PARTS\MS_GATE_Library.schlib; Mfr_name: TEXAS INSTRUMENTS; Mistral Part No: 141021010013-R; Package: SON6; Part_type: ICS\DIGITAL\GATES; Project: AM64X_SKEVM; RoHS: RoHS; Temperature: -40°C+125°C; Tolerance: NA; Voltage: NA; Wattage: NA; Weight: 33mg; Datasheet: Y:\MIS_DATABASE\DATASHEETS\ICS\DIGITAL\GATES\SN74LVC1G_NOV16.PDF
U37 = TPS22965DSGT_WSON8: IC 5.7V 6A 1-CHANNEL 16mE ON-RESISTANCE LOAD SWITCH WSON8; Chkd/date: MANIRAJA/080817; Crtd /date: VASANTHA/280714; Custom_Duty: 15%; Customs_HS_Code: 85423100; Distributor_name: DIGIKEY; Distributor_part_number: 296-34943-1-ND; Footprint Path: Y:\MIS_DATABASE\Library\ALTIUM_TOOL\PCB_FOOTPRINTS\Altium_Footprint_Lib.PcbLib; Height: 0.80MM; Library Path: Y:\MIS_DATABASE\Library\ALTIUM_TOOL\SCHEMATICS_PARTS\MS_MISCPOWER_Library.schlib; Mfr_name: TEXAS INSTRUMENTS; Mistral Part No: 142014070020-R; Package: WSON8; Part_type: ICS\POWER\DRIVER; Project: DC_MIST_DIGITAL CARD; RoHS: RoHS; Temperature: -40°C+105°C; Tolerance: NA; Voltage: NA; Wattage: NA; Weight: 11mg; Datasheet: Y:\MIS_DATABASE\DATASHEETS\ICS\POWER\TPS22965-SER.PDF
Y3 = CRY: CRY 32.768KHz 9pF SMD; Chkd/date: VASANTHA/090419; Crtd /date: ALVY/090419; Custom_Duty: 24%; Customs_HS_Code: 85439000; Distributor_name: DIGIKEY; Distributor_part_number: XC2160CT-ND; Footprint Path: Y:\MIS_DATABASE\Library\ALTIUM_TOOL\PCB_FOOTPRINTS\Altium_Footprint_Lib.PcbLib; Height: 0.90MM; Library Path: Y:\MIS_DATABASE\Library\ALTIUM_TOOL\SCHEMATICS_PARTS\MS_DISCRETE_Library.schlib; Mfr_name: ECS INC; Mfr_part_number: ECS-.327-9-34QCS-TR; Mistral Part No: 130019040003-R; Package: SMD; Part_type: CRYSTAL; Project: J7ES_SOM_DUAL-LEO_PMIC; RoHS: RoHS; Temperature: -40°C+125°C; Tolerance: NA; Voltage: NA; Wattage: NA; Weight: 16mg; Datasheet: Y:\MIS_DATABASE\DATASHEETS\MISC\CRY_OSC\ECS-34Q.PDF
C34 C37 C64 C66 C69 C71 C79 C80 C90 C385 C388 C389 C392-C397 = CAP: CAP CERAMIC 0.1uF 50V 10% X7R 0402; Alt_Mfr_name: YAGEO AMERICA; Alt_Mfr_part_number: CC0402KRX5R8BB104; Chkd/date: MANIRAJA/261020; Crtd /date: ALVY/211020; Custom_Duty: 15%; Customs_HS_Code: 85322990; Distributor_name: DIGIKEY; Distributor_part_number: 490-10700-1-ND; Footprint Path: Y:\MIS_DATABASE\Library\ALTIUM_TOOL\PCB_FOOTPRINTS\Altium_Footprint_Lib.PcbLib; Height: 0.55MM; Library Path: Y:\MIS_DATABASE\Library\ALTIUM_TOOL\SCHEMATICS_PARTS\MS_DISCRETE_Library.schlib; Mfr_name: MURATA; Mfr_part_number: GRM155R71H104KE14D; Mistral Part No: 120011100014-R; Package: 0402; Part_type: CAPACITORS\CERAMIC; Project: J7_CP; RoHS: RoHS; Temperature: -55°C+125°C; Tolerance: 10%; Voltage: 50V; Wattage: NA; Weight: 3.1mg; Datasheet: Y:\MIS_DATABASE\DATASHEETS\CAPACITORS\GRM155R71H104KE14.PDF
R66 R72 R102 R103 R375 R376 R378-R383 = RESISTOR: RES 0E 1/10W JUMPER 0402; Chkd/date: VASANTHA/061216; Crtd /date: NAVEED/201014; Custom_Duty: 15%; Customs_HS_Code: 85332119; Distributor_name: DIGIKEY; Distributor_part_number: P0.0JCT-ND; Footprint Path: Y:\MIS_DATABASE\Library\ALTIUM_TOOL\PCB_FOOTPRINTS\Altium_Footprint_Lib.PcbLib; Height: 0.40MM; IBISSP_MODLES: VALUE REPEATING 2 TIME; Library Path: Y:\MIS_DATABASE\Library\ALTIUM_TOOL\SCHEMATICS_PARTS\MS_DISCRETE_Library.schlib; Mfr_name: PANASONIC-ECG; Mfr_part_number: ERJ-2GE0R00X; Mistral Part No: 110018030052-R; Package: 0402; Part_type: RESISTORS\FIXED; Project: AEGIS POM; RoHS: RoHS; Temperature: -55°C+155°C; Tolerance: NA; Voltage: NA; Wattage: 1/10W; Weight: 0.8mg; Datasheet: Y:\MIS_DATABASE\DATASHEETS\RESISTORS\PAN-ERJSER_NOV17.PDF
R68 = RESISTOR: RES 10K 1/20W 1% 0201; Chkd/date: VASANTHA/270117; Crtd /date: MANIRAJA/270117; Custom_Duty: 15%; Customs_HS_Code: 85332119; Distributor_name: DIGIKEY; Distributor_part_number: 311-10.0KMCT-ND; Footprint Path: Y:\MIS_DATABASE\Library\ALTIUM_TOOL\PCB_FOOTPRINTS\Altium_Footprint_Lib.PcbLib; Height: 0.26MM; Library Path: Y:\MIS_DATABASE\Library\ALTIUM_TOOL\SCHEMATICS_PARTS\MS_DISCRETE_Library.schlib; Mfr_name: YAGEO AMERICA; Mfr_part_number: RC0201FR-0710KL; Mistral Part No: 110011040018-R; Package: 0201; Part_type: RESISTORS\FIXED; Project: GOLDEN-I LITE; RoHS: RoHS; Temperature: -55°C+125°C; Tolerance: 1%; Voltage: NA; Wattage: 1/20W; Weight: 0.17mg; Datasheet: Y:\MIS_DATABASE\DATASHEETS\RESISTORS\RCXXXXL-SER_MAR18.PDF
R94 R120 R132 R356 = RESISTOR-4TERM: RES 0.01E 1W 1% 1206-4; Chkd/date: MANIRAJA/060318; Crtd /date: MANIRAJA/060318; Custom_Duty: 15%; Customs_HS_Code: 85332119; Distributor_name: DIGIKEY; Distributor_part_number: 408-1974-1-ND; Footprint Path: Y:\MIS_DATABASE\Library\ALTIUM_TOOL\PCB_FOOTPRINTS\Altium_Footprint_Lib.PcbLib; Height: 0.70MM; Library Path: Y:\MIS_DATABASE\Library\ALTIUM_TOOL\SCHEMATICS_PARTS\MS_DISCRETE_Library.schlib; Manufacturer: SUSUMU; Mfr_name: SUSUMU; Mfr_part_number: KRL3216T4A-M-R010-F-T1; Mistral Part No: 110018030003-R; Package: 1206-4; Part_type: RESISTORS\FIXED; Project: GRACO SMART MODULE; RoHS: RoHS; Temperature: -55°C+155°C; Tolerance: 1%; Voltage: NA; Wattage: 1W; Weight: 16.2mg; Datasheet: Y:\MIS_DATABASE\DATASHEETS\RESISTORS\KRL-SERIES.PDF
R101 R131 = RESISTOR-4TERM: RES CURRENT SENSE 0.001E 1W 1% 0612-4; Chkd/date: MANIRAJA/261018; Crtd /date: ALVY/261018; Custom_Duty: 15%; Customs_HS_Code: 85332119; Distributor_name: DIGIKEY; Distributor_part_number: CST0612-FC-R001ECT-ND; Footprint Path: Y:\MIS_DATABASE\Library\ALTIUM_TOOL\PCB_FOOTPRINTS\Altium_Footprint_Lib.PcbLib; Height: 0.85MM; Library Path: Y:\MIS_DATABASE\Library\ALTIUM_TOOL\SCHEMATICS_PARTS\MS_DISCRETE_Library.schlib; Mfr_name: BOURNS; Mfr_part_number: CST0612-FC-R001E; Mistral Part No: 110018100018-R; Package: 0612-4; Part_type: RESISTORS\FIXED; Project: TI_J7ES_EVM_SOM; RoHS: RoHS; Temperature: -55°C+170°C; Tolerance: 1%; Voltage: NA; Wattage: 1W; Weight: 13.2mg; Datasheet: Y:\MIS_DATABASE\DATASHEETS\RESISTORS\CST0612-SERIES.PDF
R110 R359 = RESISTOR: RES 0E 1/4W JUMPER 0603 (HP); Chkd/date: USMAN/170112; Crtd /date: CHAITHANYA/170112; Custom_Duty: 15%; Customs_HS_Code: 85332119; Distributor_name: DIGIKEY; Distributor_part_number: 541-0.0SBCT-ND; Footprint Path: Y:\MIS_DATABASE\Library\ALTIUM_TOOL\PCB_FOOTPRINTS\Altium_Footprint_Lib.PcbLib; Height: 0.55MM; Library Path: Y:\MIS_DATABASE\Library\ALTIUM_TOOL\SCHEMATICS_PARTS\MS_DISCRETE_Library.schlib; Mfr_name: VISHAY; Mfr_part_number: CRCW06030000Z0EAHP; Mistral Part No: 110012010013-R; Package: 0603; Part_type: RESISTORS\FIXED; Project: NA10NG; Remarks: This part is pulse proof, high power; RoHS: RoHS; Temperature: -55°C+155°C; Tolerance: NA; Voltage: NA; Wattage: 1/4 W; Weight: 2mg; Datasheet: Y:\MIS_DATABASE\DATASHEETS\RESISTORS\CRCWXXX-HP_SEP16.PDF
U17 U25 U82-U85 = INA231_DSBGA12: IC HIGH OR LOW SIDE MEASUREMENT BI-DIR CURRENT AND POWER MONITOR WITH 1.8V I2C INTERFACE DSBGA12; Chkd/date: MANIRAJA/250821; Crtd /date: ALVY/250821; Custom_Duty: 15%; Customs_HS_Code: 85423100; Distributor_name: DIGIKEY; Distributor_part_number: 296-49645-1-ND; Footprint Path: Y:\MIS_DATABASE\Library\ALTIUM_TOOL\PCB_FOOTPRINTS\Altium_Footprint_Lib.PcbLib; Height: 0.40MM; Library Path: Y:\MIS_DATABASE\Library\ALTIUM_TOOL\SCHEMATICS_PARTS\MS_MISCPOWER_Library.schlib; Mfr_name: TEXAS INSTRUMENTS; Mistral Part No: 142021080022-R; Package: DSBGA12; Part_type: ICS\POWER\MANAGEMENT; Project: TI_AM62x SVB_BRD; RoHS: RoHS; Temperature: -40°C+125°C; Tolerance: NA; Voltage: NA; Wattage: NA; Weight: 200mg; Datasheet: Y:\MIS_DATABASE\DATASHEETS\ICS\POWER\INA231XXX.PDF

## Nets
DGND: C37.2 C64.1 C66.1 C70.2 C71.2 C72.2 C73.2 C74.2 C76.2 C77.2 C78.2 C79.1 C80.1 C81.2 C82.2 C83.2 C84.2 C85.1 C86.2 C88.1 C89.1 C90.1 C91.2 C92.2 C93.2 C94.2 C97.2 C98.2 C99.2 C100.2 C106.1 C107.1 C108.2 C109.1 C301.2 C317.2 C318.2 C319.2 C329.2 C330.2 C334.2 C340.2 C344.2 C349.2 C350.2 C354.2 C360.2 C361.2 C368.2 C372.2 C376.2 C380.2 C381.2 C382.2 C383.2 C386.2 C387.2 C388.2 C389.1 C390.2 C391.2 C395.2 C396.2 C397.2 J9.2 Q12.2(S) R400.1 R619.1 TP8.1(TP) U17.B3(A0) U17.C1(GND) U25.B3(A0) U25.C1(GND) U25.C3(A1) U27.5(REFGND1) U27.6(REFGND2) U27.21(FB_B2) U27.36(VBACKUP) U27.42(GPIO10) U27.51(GND) U27.52(NC) U27.57(GND) U31.5(GND) U31.9(~{EN}) U36.2(GND) U37.5(GND) U37.9(EP) U82.C1(GND) U83.C1(GND) U84.C1(GND) U84.C3(A1) U85.C1(GND) ; also on sheet 9 10 11 14 15 16 17 18 19 20 21 22 23 24 25 26 27 28 29 30 31 32 33 34 35 36 37 38 39 40 41 42 43
VCC1V1: C90.2 C94.1 C97.1 C98.1 C390.1 L6.2 R131.4 TP39.1(TP)
VCC1V1_SW: L6.1 U27.55(SW_B4A) U27.56(SW_B4B)
VCC1V8_SYS: C78.1 C80.2 C334.1 C340.1 C349.1 C361.1 L3.2 R120.2 TP32.1(TP) U27.10(PVIN_LDO3) ; also on sheet 17 18 20 33 36 38 39 41
VCC1V8_SYS_SW: L3.1 U27.34(SW_B5A)
VCC_0V85: C82.1 R359.1 TP30.1(TP) U27.9(VOUT_LDO3)
VCC_3V3_MAIN: C76.1 C77.1 C83.1 C88.2 C91.1 C92.1 C107.2 C108.1 C109.2 C329.1 C330.1 C344.1 C354.1 C360.1 C368.1 C372.1 C376.1 C380.1 C383.1 C386.1 C387.1 R138.2 R401.2 TP48.1(TP) U27.4(VCCA) U27.8(PVIN_LDO4) U27.12(PVIN_LDO12) U27.17(PVIN_B2) U27.26(PVIN_B1) U27.35(PVIN_B5) U27.45(PVIN_B3) U27.48(VIO_IN) U27.54(PVIN_B4) U31.10(VCC) U36.5(VCC) U37.1(VIN1) U37.2(VIN2) U37.4(VBIAS) ; also on sheet 11 14 25
VCC_3V3_MAIN_PG: U36.3(B) ; also on sheet 10 11
VCC_3V3_SYS: C37.1 C66.2 C71.1 C106.2 C388.1 C395.1 C396.1 C397.1 R68.2 R87.2 R94.2 R126.2 R222.2 R492.2 R501.2 R618.2 TP47.1(TP) U17.B1(VS) U25.B1(VS) U37.7(VOUT1) U37.8(VOUT2) U82.B1(VS) U82.B3(A0) U82.C3(A1) U83.B1(VS) U83.B3(A0) U84.B1(VS) U84.B3(A0) U85.B1(VS) U85.C3(A1) ; also on sheet 9 10 17 18 19 21 22 23 25 26 28 29 30 32 33 34 35 36 37 38 39 40 41 42
VCC_3V3_SYS_EN: R398.2 R400.2 R401.1 R575.2 TP53.1(TP) U27.47(GPIO4) U37.3(ON)
VCC_5V0_EN: R398.1 ; also on sheet 10
VCC_CORE: C64.2 C70.1 C72.1 C73.1 C74.1 C93.1 C99.1 C100.1 C301.1 C317.1 C318.1 C319.1 C391.1 L1.2 L2.2 L5.2 R101.4 R110.1 TP25.1(TP)
VDD_CANUART_EN: R575.1 ; also on sheet 14
VDD_CORE: R101.1 U27.22(FB_B1) ; also on sheet 14 15
VDD_CORE_REG_SW1: L1.1 U27.27(SW_B1A) U27.28(SW_B1B)
VDD_CORE_REG_SW2: L2.1 U27.15(SW_B2A) U27.16(SW_B2B)
VDD_CORE_REG_SW3: L5.1 U27.43(SW_B3A) U27.44(SW_B3B)
VDD_LPDDR4: R131.1 U27.50(FB_B4) ; also on sheet 14 15 16
VDDA1V8: C84.1 C389.2 R132.2 TP40.1(TP) U27.7(VOUT_LDO4)
VDDA_1V8: R132.3 ; also on sheet 14 15 24
VDDR_CORE: R356.3 ; also on sheet 14 15 35
VDDSHV_SDIO: C350.1 TP34.1(TP) U27.13(VOUT_LDO1) ; also on sheet 14 19
VINT_PMIC_1V8: C382.1 TP101.1(TP) U27.2(VOUT_LDOVINT)
CAN_IO_3V3: R139.2 R140.2 ; also on sheet 14 30 33 43
CORE_PWR_STRAP: R618.1 R619.2 U27.24(GPIO6)
EN_DRV_OUT: TP31.1(TP) U27.29(EN_DRV)
INA_ALERT: R67.2 R68.1 R109.2 R377.2 R385.2 R386.2 R387.2 TP38.1(TP)
LDO_3V3: U27.49(FB_B3) ; also on sheet 9
MCU_I2C0_SCL: U27.32(GPIO1) ; also on sheet 33
MCU_I2C0_SDA: R137.2 U27.33(GPIO2) ; also on sheet 33
MCU_INTn: R123.1 ; also on sheet 33
MCU_SAFETY_ERRORz_3V3: U27.18(GPIO7) ; also on sheet 33
MMC1_SDCARD_EN: R374.1 ; also on sheet 19
PMIC_AMUXOUT: TP36.1(TP) U27.1(AMUXOUT)
PMIC_ENABLE: TP42.1(TP) U31.4(A) U36.1(A)
PMIC_ENABLE_SEL: J9.1 R138.1 U31.1(SEL)
PMIC_INT_B: R123.2 R126.1 R127.2 TP33.1(TP) U27.14(nINT)
PMIC_INTn: R127.1 ; also on sheet 41
PMIC_LPM_EN0: R140.1 U31.3(A1) U31.8(B0) ; also on sheet 31
PMIC_nPWRON/ENABLE: R148.2 U27.20(nPWRON/ENABLE)
PMIC_nSLEEP: U27.46(GPIO3) U31.6(B)
PMIC_OSC32KCAP: C381.1 U27.40(OSC32KCAP)
PMIC_OSC32KIN: C85.2 U27.38(OSC32KIN) Y3.2
PMIC_OSC32KOUT: C89.2 U27.39(OSC32KOUT) Y3.1
PMIC_POWERGOOD: R500.1 R501.1 TP81.1(TP) U27.25(nRSTOUT) ; also on sheet 41
PMIC_WDOG_DISABLE: R492.1 TP74.1(TP) U27.41(GPIO8) ; also on sheet 27
PMIC_WDOG_TRIGG: R137.1 ; also on sheet 31
SOC_DVDD1V8: R120.3 U27.37(FB_B5) ; also on sheet 14 15 16
SoC_DVDD3V3: R94.3 ; also on sheet 14 15
SoC_I2C0_SCL: R363.1 ; also on sheet 9 21 32 41
SoC_I2C0_SCL_PMIC: R363.2 TP43.1(TP) U27.31(SCL_I2C1/SCK_SPI)
SoC_I2C0_SDA: R362.1 ; also on sheet 9 21 32 41
SoC_I2C0_SDA_PMIC: R362.2 TP44.1(TP) U27.30(SDA_I2C1/SDI_SPI)
SOC_I2C1_SCL: U17.A1(SCL) U17.C3(A1) U25.A1(SCL) U82.A1(SCL) U83.A1(SCL) U83.C3(A1) U84.A1(SCL) U85.A1(SCL) U85.B3(A0) ; also on sheet 21 25 38 39 40 41
SOC_I2C1_SDA: U17.A2(SDA) U25.A2(SDA) U82.A2(SDA) U83.A2(SDA) U84.A2(SDA) U85.A2(SDA) ; also on sheet 21 25 38 39 40 41
TEST_POWERDOWN: U36.6(C) ; also on sheet 10 25 27
TPS6593_EN: R148.1 U36.4(Y)
VPP_1V8: C81.1 TP35.1(TP) U27.11(VOUT_LDO2) ; also on sheet 14
VPP_EN: U27.19(GPIO9) ; also on sheet 39
VRTC_PMIC_1V8: C86.1 TP37.1(TP) U27.3(VOUT_LDOVRTC)
VSEL_SD_SOC: R87.1 TP19.1(TP) U27.23(GPIO5) ; also on sheet 31
N16839912: C385.1 R375.1 U82.D3(IN+)
N16839940: C392.1 R378.1 U83.D3(IN+)
N16839975: C394.1 R382.1 U85.D3(IN+)
N17153379: R101.3 R102.2
N17153381: R101.2 R103.2
N17153383: C79.2 R110.2 R356.2 R359.2
N17153415: R356.1 R380.2
N17153417: R356.4 R381.2
N17153507: R66.2 R94.1
N17153509: R72.2 R94.4
N17153511: C34.2 R72.1 U17.D1(BUS) U17.D2(IN-)
N17153515: C34.1 R66.1 U17.D3(IN+)
N17153617: R120.1 R375.2
N17153619: R120.4 R376.2
N17153623: R132.1 R378.2
N17153625: R132.4 R379.2
N17153667: R131.3 R382.2
N17153669: R131.2 R383.2
N17153681: C69.1 R102.1 U25.D3(IN+)
N17153685: C69.2 R103.1 U25.D1(BUS) U25.D2(IN-)
N17153701: C393.2 R381.1 U84.D1(BUS) U84.D2(IN-)
N17153703: C393.1 R380.1 U84.D3(IN+)
N17153749: C385.2 R376.1 U82.D1(BUS) U82.D2(IN-)
N17153787: C392.2 R379.1 U83.D1(BUS) U83.D2(IN-)
N17153799: C394.2 R383.1 U85.D1(BUS) U85.D2(IN-)
N17153878: R385.1 U84.A3(ALERT)
N17153949: R377.1 U82.A3(ALERT)
N17153951: R386.1 U83.A3(ALERT)
N17154063: R387.1 U85.A3(ALERT)
N18516151: R109.1 U25.A3(ALERT)
N18520654: R67.1 U17.A3(ALERT)
N19361712: LD7.1(CATHODE) Q12.3(D)
N22373538: R139.1 U31.2(A0) U31.7(B1)
N22885689: R374.2 U27.53(GPIO11)
N24413846: Q12.1(G) R500.2
N24413847: LD7.2(ANODE) R222.1

Not connected (* = marked no-connect by the designer): U17 B2(NC1)* C2(NC2)*; U25 B2(NC1)* C2(NC2)*; U37 6(CT)*; U82 B2(NC1)* C2(NC2)*; U83 B2(NC1)* C2(NC2)*; U84 B2(NC1)* C2(NC2)*; U85 B2(NC1)* C2(NC2)*

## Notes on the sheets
sheet 12
- SOC POWER SUPPLY PMIC
- PMIC Config option
- Cad Note :-
  Tie the feedback after the
  DC/DC output bulk caps or
  use remote sensing
- Route as Pseudo differential pair trace
- (See "PCB Notes")
- D-Note :-
  Add a 0R resistor or
  Jumper at the output
  of the DC/DC  for
  isolation or testing
- FB_VDD_CORE_P
- Capacitors C318, C317, C391,
  C390 & C340
  are marked DNP to meet
  PMIC output cap specifications
- FB_VDD_CORE_N
- D-Note :-
  Use 10V rated caps to take care
  of the DC bias and derating
- R-Note :-
  SD card interface IO
  voltage switching
  (3.3V/1.8V) is required to
  support higher speed data
  rates. Refer SOC data sheet
  for supported rates and IO
  voltage levels
- PMIC uses default I2C0 ADDR: 0x48,0x49, 0x5A, 0x5B
- VCC_3V3_SYS LOAD SWITCH
- R-Note :-
  CORE_PWR_STRAP/ GPIO6
  High: Buck1/2/3 = 0.85V
  LOW/Floating: Buck1/2/3
  = 0.75V
- POWER
  INDICATION LED
- D-Note :-
  Add a cap (>220 pF) to
  the CT pin for SOC IO
  supply slew rate
  control. SOC IO supplies
  have slew rate
  requirements specified
sheet 13
- CURRENT MONITORING DEVICES
- VDD_CORE
- SoC_DVDD1V8
- D-Note :-
  Note the supply rail name change across
  the shunt when optimizing the design
  (Deleting the current sense resistor)
- CAD Note :-
  Follow Kelvin
  connection for
  Current Sensing
  when using 2
  terminal resistors
- I2C ADDRESS: 0x40
- I2C ADDRESS: 0x45
- VDDR_CORE
- VDDA_1V8
- Mount R359 & Demount R110
  when VCC_CORE is 0.75V
- I2C ADDRESS: 0x4D
- I2C ADDRESS: 0x41
- SoC_DVDD3V3
- VDD_LPDDR4
- I2C ADDRESS: 0x4C
- I2C ADDRESS: 0x47
- INA I2C SLAVE ADDRESS
- SLAVE
  ADDRESS
  (IN HEX)
- POWER SOURCE
- SUPPLY NET
- VCC_CORE
- VDD_CORE
- 40
- VCC_0V85
- VDDR_CORE
- 41
- VCC_3V3_SYS
- SoC_DVDD3V3
- 4C
- VCC_1V8
- SoC_DVDD1V8
- 45
- VDDA1V8
- VDDA_1V8
- 4D
- VCC1V1
- VDD_LPDDR4
- 47
